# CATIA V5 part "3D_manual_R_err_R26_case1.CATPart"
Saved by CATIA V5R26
Part number: 3D_manual_R_err
Description: Copyright©3D-raku.com  Copyright©CATIAmaster.xyz
Bounding box of the stored display mesh (mm): x 36.39 to 126.419, y -15.123 to 37.571, z -20 to 13
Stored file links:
  F:\Dropbox\ina-catia_web\CATIA-master\CATIAデータ\3D_manual_R_err\3D_manual_R_err_R26_case1.CATPart
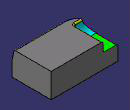
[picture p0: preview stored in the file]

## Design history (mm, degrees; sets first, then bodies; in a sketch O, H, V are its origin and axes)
Body1
  Sketch1 on xy-plane, origin (0, 0, 0), H (1, 0, 0), V (0, 1, 0)
    line L1 (36.3899, 37.5714) -> (126.4194, 37.5714)
    line L2 (126.4194, 37.5714) -> (126.4194, -15.1231)
    line L3 (126.4194, -15.1231) -> (59.1167, -15.1231)
    line L4 (36.3899, 7.6038) -> (36.3899, 37.5714)
    arc A1 centre (59.1167, 7.6038) radius 22.7269 from (59.1167, -15.1231) to (36.3899, 7.6038) cw
    radius A1 = 22.7269
    horizontal: L1 H, L3 H
    vertical: L2 V, L4 V
    tangency: A1 L3, A1 L4
  Pad1: profile Sketch1, direction (0, 0, -1), length 20, opposite side length 13
  Draft1: Angle 11, Neutral xy-plane, PullDir xy-plane, SupportToDraft face of Pad1 from Sketch1.L3
  Fillet1: radius 3, on edge [face of Pad1 from Sketch1.A1 | face of Pad1 from Sketch1.A1]
  Body2
    Sketch2 on xy-plane, origin (0, 0, 0), H (1, 0, 0), V (0, 1, 0)
      line L1 (18.6626, 44.6458) -> (56.3899, 44.6458)
      line L2 (56.3899, 44.6458) -> (56.3899, -2.1231)
      line L3 (56.3899, -2.1231) -> (18.6626, -2.1231)
      line L4 (18.6626, -2.1231) -> (18.6626, 44.6458)
      reference projected line E1 (59.1167, -15.1231) -> (126.4194, -15.1231) from Sketch1.L3
      reference projected line E2 (36.3899, 37.5714) -> (36.3899, 7.6038) from Sketch1.L4
      distance E1 L3 = 13
      distance L2 E2 = 20
      horizontal: L1 H, L3 H
      vertical: L2 V, L4 V
    Pad2: profile Sketch2, direction (0, 0, 1), length 20
    Fillet2: radius 12, on edge [start face of Pad2 | face of Pad2 from Sketch2.L3]
  Remove1: tool Body2
  Fillet3: radius 2, on edge [face of Fillet2 | face of Pad1 from Sketch1.A1]
  Fillet4: radius 2, on edge [face of Pad2 from Sketch2.L2 | start face of Pad2]
  Fillet5: radius 2, on edge [start face of Pad1 | face of Pad2 from Sketch2.L2]
Body3 (main body)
